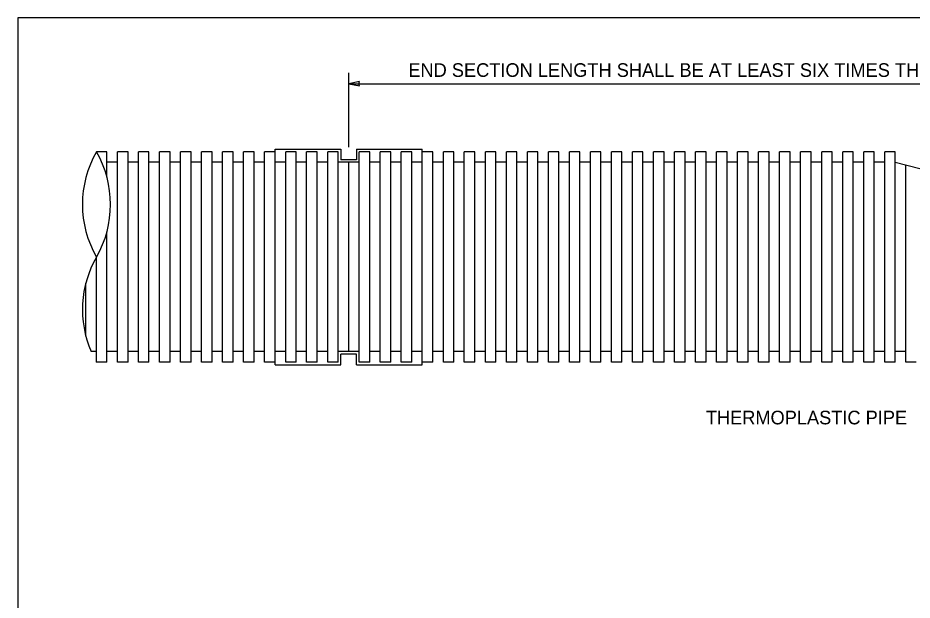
# Model space of a CAD drawing. Extents: x 99862 to 103680, y 99470 to 102076.
# Drawn here: x 99862 to 101176, y 101221 to 102076 of the extents above; entities that cross this region are included whole.
import ezdxf

# ---------------------------------------------------------------- set-up
doc = ezdxf.new("R2010")
doc.units = 0
for name, color, linetype in [('Default', 7, 'Continuous'), ('Level 1', 7, 'Continuous'), ('Level 15', 7, 'Continuous'), ('Level 20', 7, 'Continuous'), ('Level 5', 7, 'Continuous'), ('Level 6', 7, 'Continuous')]:
    doc.layers.add(name, color=color, linetype=linetype)

msp = doc.modelspace()

# ---------------------------------------------------------------- linework, layer by layer
at = {"layer": 'Default'}
msp.add_lwpolyline([(100348, 101978.9), (100363.7, 101975.8), (100363, 101978.9), (100363.7, 101982)], close=True, dxfattribs=at)
at = {"layer": 'Level 1'}
msp.add_lwpolyline([(99862, 99999.5), (103151, 99999.5), (103151, 102075.5), (99862, 102075.5)], close=True, dxfattribs=at)
at = {"layer": 'Level 15'}
for p, q in [((100348, 101885.8), (100348, 101994.9)), ((100348, 101978.9), (102015.5, 101978.9))]:
    msp.add_line(p, q, dxfattribs=at)
at = {"layer": 'Level 5'}
for p, q in [((100008.3, 101570.1), (100008.3, 101878.9)), ((100023.8, 101570.1), (100023.8, 101878.9)), ((100039.2, 101570.1), (100039.2, 101878.9)), ((100054.6, 101570.1), (100054.6, 101878.9)), ((100070.1, 101570.1), (100070.1, 101878.9)), ((100085.5, 101570.1), (100085.5, 101878.9)), ((100101, 101570.1), (100101, 101878.9)), ((100116.4, 101570.1), (100116.4, 101878.9)), ((100131.8, 101570.1), (100131.8, 101878.9)), ((100147.3, 101570.1), (100147.3, 101878.9)), ((100162.7, 101570.1), (100162.7, 101878.9)), ((100178.2, 101570.1), (100178.2, 101878.9)), ((100193.6, 101570.1), (100193.6, 101878.9)), ((100209, 101570.1), (100209, 101878.9)), ((100224.5, 101570.1), (100224.5, 101878.9)), ((100239.9, 101566.2), (100239.9, 101882.7)), ((100255.4, 101570.1), (100255.4, 101878.9)), ((100270.8, 101570.1), (100270.8, 101878.9)), ((100286.2, 101570.1), (100286.2, 101878.9)), ((100301.7, 101570.1), (100301.7, 101878.9)), ((100317.1, 101570.1), (100317.1, 101878.9)), ((100332.6, 101570.1), (100332.6, 101878.9)), ((100363.4, 101570.1), (100363.4, 101878.9)), ((100378.9, 101570.1), (100378.9, 101878.9)), ((100394.3, 101570.1), (100394.3, 101878.9)), ((100409.8, 101570.1), (100409.8, 101878.9)), ((100425.2, 101570.1), (100425.2, 101878.9)), ((100440.6, 101570.1), (100440.6, 101878.9)), ((100456.1, 101566.2), (100456.1, 101882.7)), ((100471.5, 101570.1), (100471.5, 101878.9)), ((100487, 101570.1), (100487, 101878.9)), ((100502.4, 101570.1), (100502.4, 101878.9)), ((100517.8, 101570.1), (100517.8, 101878.9)), ((100533.3, 101570.1), (100533.3, 101878.9)), ((100548.7, 101570.1), (100548.7, 101878.9)), ((100564.2, 101570.1), (100564.2, 101878.9)), ((100579.6, 101570.1), (100579.6, 101878.9)), ((100595, 101570.1), (100595, 101878.9)), ((100610.5, 101570.1), (100610.5, 101878.9)), ((100625.9, 101570.1), (100625.9, 101878.9)), ((100641.4, 101570.1), (100641.4, 101878.9)), ((100656.8, 101570.1), (100656.8, 101878.9)), ((100672.2, 101570.1), (100672.2, 101878.9)), ((100687.7, 101570.1), (100687.7, 101878.9)), ((100703.1, 101570.1), (100703.1, 101878.9)), ((100718.6, 101570.1), (100718.6, 101878.9)), ((100734, 101570.1), (100734, 101878.9)), ((100749.4, 101570.1), (100749.4, 101878.9)), ((100764.9, 101570.1), (100764.9, 101878.9)), ((100780.3, 101570.1), (100780.3, 101878.9)), ((100795.8, 101570.1), (100795.8, 101878.9)), ((100811.2, 101570.1), (100811.2, 101878.9)), ((100826.6, 101570.1), (100826.6, 101878.9)), ((100842.1, 101570.1), (100842.1, 101878.9)), ((100857.5, 101570.1), (100857.5, 101878.9)), ((100873, 101570.1), (100873, 101878.9)), ((100888.4, 101570.1), (100888.4, 101878.9)), ((100903.8, 101570.1), (100903.8, 101878.9)), ((100919.3, 101570.1), (100919.3, 101878.9)), ((100934.7, 101570.1), (100934.7, 101878.9)), ((100950.2, 101570.1), (100950.2, 101878.9)), ((100965.6, 101570.1), (100965.6, 101878.9)), ((100981, 101570.1), (100981, 101878.9)), ((100996.5, 101570.1), (100996.5, 101878.9)), ((101011.9, 101570.1), (101011.9, 101878.9)), ((101027.4, 101570.1), (101027.4, 101878.9)), ((101042.8, 101570.1), (101042.8, 101878.9)), ((101058.2, 101570.1), (101058.2, 101878.9)), ((101073.7, 101570.1), (101073.7, 101878.9)), ((101089.1, 101570.1), (101089.1, 101878.9)), ((101104.6, 101570.1), (101104.6, 101878.9)), ((101120, 101570.1), (101120, 101878.9)), ((101135.4, 101570.1), (101135.4, 101878.9)), ((101150.9, 101570.1), (101150.9, 101878.9)), ((100008.3, 101863.4), (99992.9, 101863.4)), ((100039.2, 101863.4), (100023.8, 101863.4)), ((100070.1, 101863.4), (100054.6, 101863.4)), ((100101, 101863.4), (100085.5, 101863.4)), ((100131.8, 101863.4), (100116.4, 101863.4)), ((100162.7, 101863.4), (100147.3, 101863.4)), ((100193.6, 101863.4), (100178.2, 101863.4)), ((100224.5, 101863.4), (100209, 101863.4)), ((100255.4, 101863.4), (100239.9, 101863.4)), ((100286.2, 101863.4), (100270.8, 101863.4)), ((100317.1, 101863.4), (100301.7, 101863.4)), ((100348, 101863.4), (100332.6, 101863.4)), ((100359.6, 101867.3), (100336.4, 101867.3)), ((100348, 101585.5), (100348, 101863.4)), ((100363.4, 101863.4), (100348, 101863.4)), ((100394.3, 101863.4), (100378.9, 101863.4)), ((100425.2, 101863.4), (100409.8, 101863.4)), ((100456.1, 101863.4), (100440.6, 101863.4)), ((100487, 101863.4), (100471.5, 101863.4)), ((100517.8, 101863.4), (100502.4, 101863.4)), ((100548.7, 101863.4), (100533.3, 101863.4)), ((100579.6, 101863.4), (100564.2, 101863.4)), ((100610.5, 101863.4), (100595, 101863.4)), ((100641.4, 101863.4), (100625.9, 101863.4)), ((100672.2, 101863.4), (100656.8, 101863.4)), ((100703.1, 101863.4), (100687.7, 101863.4)), ((100734, 101863.4), (100718.6, 101863.4)), ((100764.9, 101863.4), (100749.4, 101863.4)), ((100795.8, 101863.4), (100780.3, 101863.4)), ((100826.6, 101863.4), (100811.2, 101863.4)), ((100857.5, 101863.4), (100842.1, 101863.4)), ((100888.4, 101863.4), (100873, 101863.4)), ((100919.3, 101863.4), (100903.8, 101863.4)), ((100950.2, 101863.4), (100934.7, 101863.4)), ((100981, 101863.4), (100965.6, 101863.4)), ((101011.9, 101863.4), (100996.5, 101863.4)), ((101042.8, 101863.4), (101027.4, 101863.4)), ((101073.7, 101863.4), (101058.2, 101863.4)), ((101104.6, 101863.4), (101089.1, 101863.4)), ((101135.4, 101863.4), (101120, 101863.4)), ((101150.9, 101863.4), (102015.5, 101647.3)), ((101166.3, 101570.1), (101166.3, 101859.6)), ((99992.9, 101570.1), (99992.9, 101761.5)), ((99977.4, 101570.1), (99977.4, 101724.2)), ((99961.7, 101607.9), (99961.7, 101686)), ((99977.4, 101585.5), (99969.4, 101585.5)), ((100008.3, 101585.5), (99992.9, 101585.5)), ((100039.2, 101585.5), (100023.8, 101585.5)), ((100070.1, 101585.5), (100054.6, 101585.5)), ((100101, 101585.5), (100085.5, 101585.5)), ((100131.8, 101585.5), (100116.4, 101585.5)), ((100162.7, 101585.5), (100147.3, 101585.5)), ((100193.6, 101585.5), (100178.2, 101585.5)), ((100224.5, 101585.5), (100209, 101585.5)), ((100255.4, 101585.5), (100239.9, 101585.5)), ((100286.2, 101585.5), (100270.8, 101585.5)), ((100317.1, 101585.5), (100301.7, 101585.5)), ((100348, 101585.5), (100332.6, 101585.5)), ((100363.4, 101585.5), (100348, 101585.5)), ((100394.3, 101585.5), (100378.9, 101585.5)), ((100425.2, 101585.5), (100409.8, 101585.5)), ((100456.1, 101585.5), (100440.6, 101585.5)), ((100487, 101585.5), (100471.5, 101585.5)), ((100517.8, 101585.5), (100502.4, 101585.5)), ((100548.7, 101585.5), (100533.3, 101585.5)), ((100579.6, 101585.5), (100564.2, 101585.5)), ((100610.5, 101585.5), (100595, 101585.5)), ((100641.4, 101585.5), (100625.9, 101585.5)), ((100672.2, 101585.5), (100656.8, 101585.5)), ((100703.1, 101585.5), (100687.7, 101585.5)), ((100734, 101585.5), (100718.6, 101585.5)), ((100764.9, 101585.5), (100749.4, 101585.5)), ((100795.8, 101585.5), (100780.3, 101585.5)), ((100826.6, 101585.5), (100811.2, 101585.5)), ((100857.5, 101585.5), (100842.1, 101585.5)), ((100888.4, 101585.5), (100873, 101585.5)), ((100919.3, 101585.5), (100903.8, 101585.5)), ((100950.2, 101585.5), (100934.7, 101585.5)), ((100981, 101585.5), (100965.6, 101585.5)), ((101011.9, 101585.5), (100996.5, 101585.5)), ((101042.8, 101585.5), (101027.4, 101585.5)), ((101073.7, 101585.5), (101058.2, 101585.5)), ((101104.6, 101585.5), (101089.1, 101585.5)), ((101135.4, 101585.5), (101120, 101585.5)), ((101166.3, 101585.5), (101150.9, 101585.5)), ((100359.6, 101581.7), (100336.4, 101581.7))]:
    msp.add_line(p, q, dxfattribs=at)
at = {"layer": 'Level 6'}
for p, q in [((99992.9, 101878.9), (99977.4, 101878.9)), ((99992.9, 101841.6), (99992.9, 101878.9)), ((100023.8, 101878.9), (100008.3, 101878.9)), ((100054.6, 101878.9), (100039.2, 101878.9)), ((100085.5, 101878.9), (100070.1, 101878.9)), ((100116.4, 101878.9), (100101, 101878.9)), ((100147.3, 101878.9), (100131.8, 101878.9)), ((100178.2, 101878.9), (100162.7, 101878.9)), ((100209, 101878.9), (100193.6, 101878.9)), ((100239.9, 101878.9), (100224.5, 101878.9)), ((100239.9, 101882.7), (100336.4, 101882.7)), ((100270.8, 101878.9), (100255.4, 101878.9)), ((100301.7, 101878.9), (100286.2, 101878.9)), ((100332.6, 101878.9), (100317.1, 101878.9)), ((100336.4, 101882.7), (100336.4, 101867.3)), ((100359.6, 101882.7), (100456.1, 101882.7)), ((100359.6, 101882.7), (100359.6, 101867.3)), ((100378.9, 101878.9), (100363.4, 101878.9)), ((100409.8, 101878.9), (100394.3, 101878.9)), ((100440.6, 101878.9), (100425.2, 101878.9)), ((100471.5, 101878.9), (100456.1, 101878.9)), ((100502.4, 101878.9), (100487, 101878.9)), ((100533.3, 101878.9), (100517.8, 101878.9)), ((100564.2, 101878.9), (100548.7, 101878.9)), ((100595, 101878.9), (100579.6, 101878.9)), ((100625.9, 101878.9), (100610.5, 101878.9)), ((100656.8, 101878.9), (100641.4, 101878.9)), ((100687.7, 101878.9), (100672.2, 101878.9)), ((100718.6, 101878.9), (100703.1, 101878.9)), ((100749.4, 101878.9), (100734, 101878.9)), ((100780.3, 101878.9), (100764.9, 101878.9)), ((100811.2, 101878.9), (100795.8, 101878.9)), ((100842.1, 101878.9), (100826.6, 101878.9)), ((100873, 101878.9), (100857.5, 101878.9)), ((100903.8, 101878.9), (100888.4, 101878.9)), ((100934.7, 101878.9), (100919.3, 101878.9)), ((100965.6, 101878.9), (100950.2, 101878.9)), ((100996.5, 101878.9), (100981, 101878.9)), ((101027.4, 101878.9), (101011.9, 101878.9)), ((101058.2, 101878.9), (101042.8, 101878.9)), ((101089.1, 101878.9), (101073.7, 101878.9)), ((101120, 101878.9), (101104.6, 101878.9)), ((101150.9, 101878.9), (101135.4, 101878.9)), ((100336.4, 101566.2), (100336.4, 101581.7)), ((100359.6, 101566.2), (100359.6, 101581.7)), ((99992.9, 101570.1), (99977.2, 101570.1)), ((100023.8, 101570.1), (100008.3, 101570.1)), ((100054.6, 101570.1), (100039.2, 101570.1)), ((100085.5, 101570.1), (100070.1, 101570.1)), ((100116.4, 101570.1), (100101, 101570.1)), ((100147.3, 101570.1), (100131.8, 101570.1)), ((100178.2, 101570.1), (100162.7, 101570.1)), ((100209, 101570.1), (100193.6, 101570.1)), ((100239.9, 101570.1), (100224.5, 101570.1)), ((100239.9, 101566.2), (100336.4, 101566.2)), ((100270.8, 101570.1), (100255.4, 101570.1)), ((100301.7, 101570.1), (100286.2, 101570.1)), ((100332.6, 101570.1), (100317.1, 101570.1)), ((100359.6, 101566.2), (100456.1, 101566.2)), ((100378.9, 101570.1), (100363.4, 101570.1)), ((100409.8, 101570.1), (100394.3, 101570.1)), ((100440.6, 101570.1), (100425.2, 101570.1)), ((100471.5, 101570.1), (100456.1, 101570.1)), ((100502.4, 101570.1), (100487, 101570.1)), ((100533.3, 101570.1), (100517.8, 101570.1)), ((100564.2, 101570.1), (100548.7, 101570.1)), ((100595, 101570.1), (100579.6, 101570.1)), ((100625.9, 101570.1), (100610.5, 101570.1)), ((100656.8, 101570.1), (100641.4, 101570.1)), ((100687.7, 101570.1), (100672.2, 101570.1)), ((100718.6, 101570.1), (100703.1, 101570.1)), ((100749.4, 101570.1), (100734, 101570.1)), ((100780.3, 101570.1), (100764.9, 101570.1)), ((100811.2, 101570.1), (100795.8, 101570.1)), ((100842.1, 101570.1), (100826.6, 101570.1)), ((100873, 101570.1), (100857.5, 101570.1)), ((100903.8, 101570.1), (100888.4, 101570.1)), ((100934.7, 101570.1), (100919.3, 101570.1)), ((100965.6, 101570.1), (100950.2, 101570.1)), ((100996.5, 101570.1), (100981, 101570.1)), ((101027.4, 101570.1), (101011.9, 101570.1)), ((101058.2, 101570.1), (101042.8, 101570.1)), ((101089.1, 101570.1), (101073.7, 101570.1)), ((101120, 101570.1), (101104.6, 101570.1)), ((101150.9, 101570.1), (101135.4, 101570.1)), ((101181.8, 101570.1), (101166.3, 101570.1))]:
    msp.add_line(p, q, dxfattribs=at)
for centre, start, end in [((100111.4, 101801.6), 150, 210), ((99843.5, 101801.6), 330, 30), ((100111.4, 101646.9), 150, 203.3977)]:
    msp.add_arc(centre, 154.6, start, end, dxfattribs=at)

# ---------------------------------------------------------------- texts
at = {"layer": 'Level 20'}
for s, p in [('END SECTION LENGTH SHALL BE AT LEAST SIX TIMES THE DIAMETER OF THE PIPE (SEE ', (100435.6, 101988.9)), ('THERMOPLASTIC PIPE', (100872.6, 101478.6))]:
    msp.add_text(s, height=20, dxfattribs=at).set_placement(p)

doc.saveas('drawing.dxf')
